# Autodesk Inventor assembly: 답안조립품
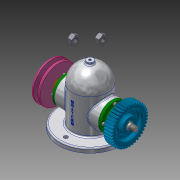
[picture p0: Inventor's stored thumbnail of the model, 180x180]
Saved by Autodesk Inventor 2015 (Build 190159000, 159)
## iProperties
Created: 2019-11
Part Number: 답안조립품
Document SubType Name: Assembly
Designer: Administrator
Author: Administrator
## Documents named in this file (13)
- C:\Users\Administrator.SC-201903271402\Desktop\491104V1026\답안조립품.iam
- C:\Users\Administrator.SC-201903271402\Desktop\491104V1026\본체.ipt
- C:\Users\Administrator.SC-201903271402\Desktop\491104V1026\축.ipt
- C:\Users\Administrator.SC-201903271402\Desktop\491104V1026\베어링 6203.ipt
- C:\Users\Administrator.SC-201903271402\Desktop\491104V1026\부시.ipt
- C:\Users\Administrator.SC-201903271402\Desktop\491104V1026\커버.ipt
- C:\Users\Administrator.SC-201903271402\Desktop\491104V1026\볼트 M4.ipt
- C:\Users\Administrator.SC-201903271402\Desktop\491104V1026\오일 실 26 38 8.ipt
- C:\Users\Administrator.SC-201903271402\Desktop\491104V1026\키 5x5x12.ipt
- C:\Users\Administrator.SC-201903271402\Desktop\491104V1026\V-벨트풀리.ipt
- V-벨트풀리.ipt
- C:\Users\Administrator.SC-201903271402\Desktop\491104V1026\스퍼기어.ipt
- C:\Users\Administrator.SC-201903271402\Desktop\491104V1026\너트 M12x1.25.ipt
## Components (1 placed, 1 different names)
1. V-벨트풀리:1
